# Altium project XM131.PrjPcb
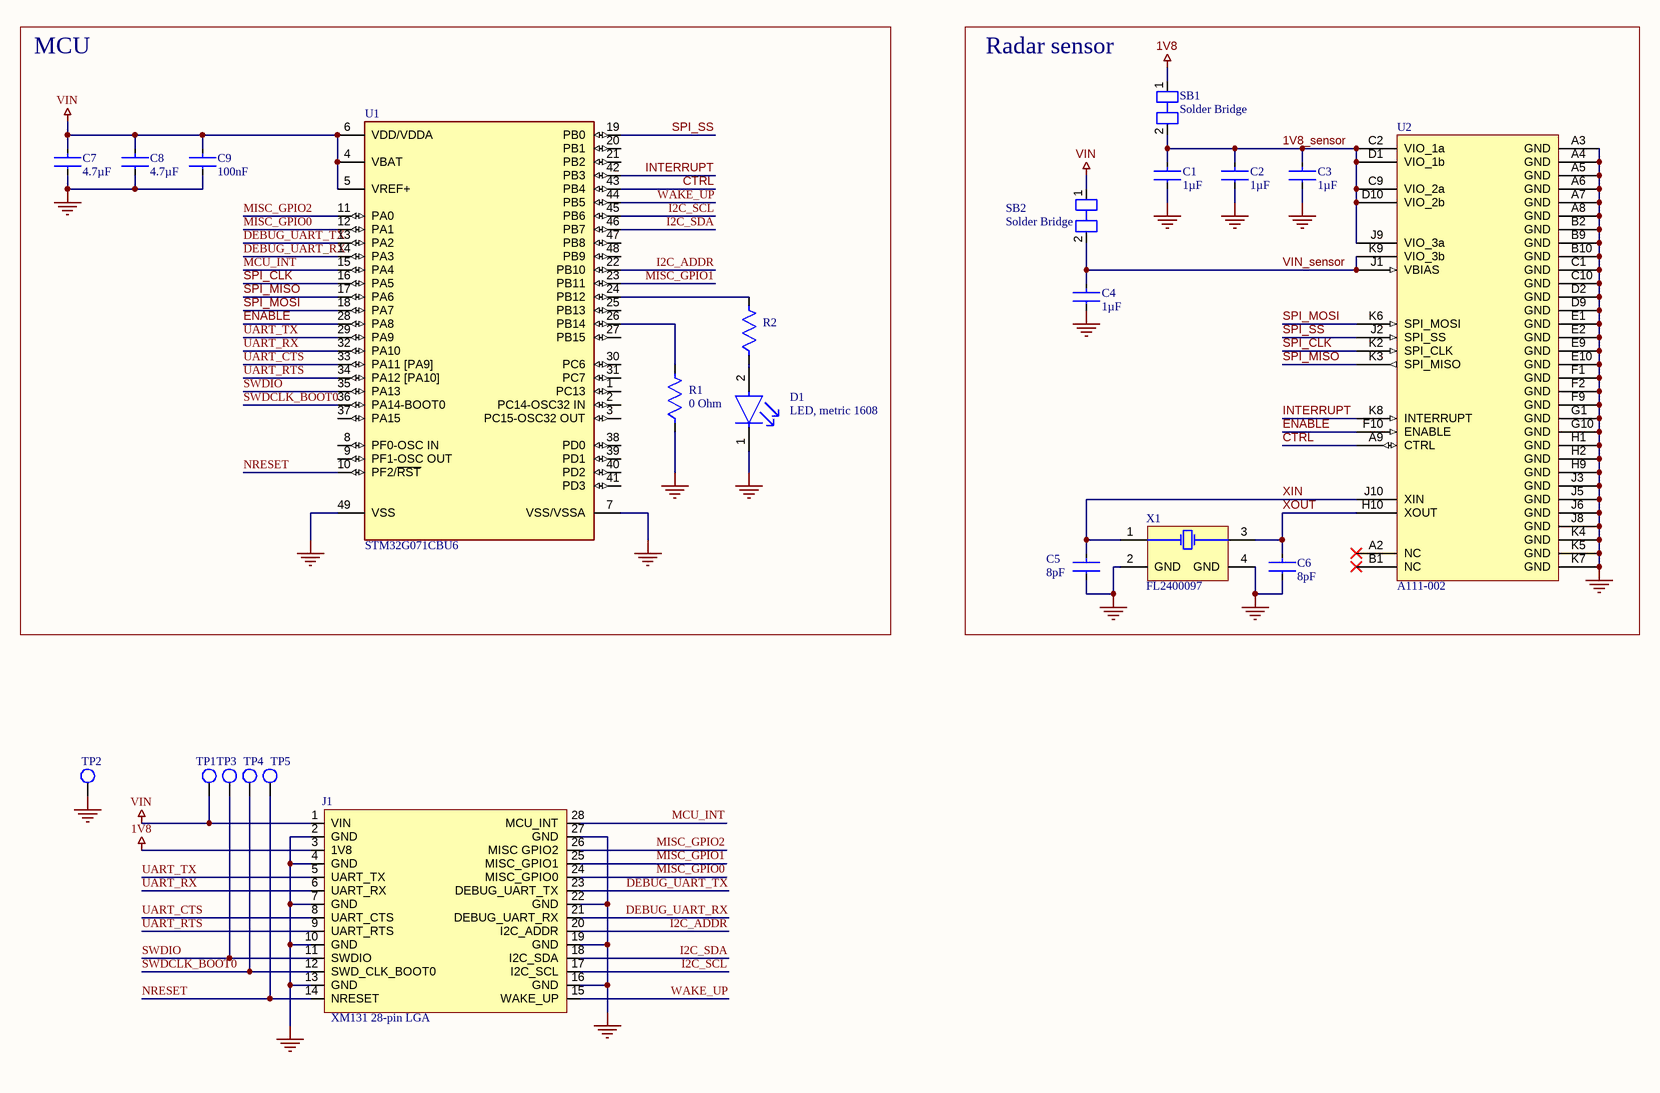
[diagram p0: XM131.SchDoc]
PCB_version: 1.1; PCBA_version: R1B; PB_number: 24
1 sheet, 23 parts. Net scope: global (net labels, ports and power ports of the same name join across sheets).
Board file: XM131.PcbDoc

## Sheet XM131.SchDoc: XM131 radar module
size 420 x 297 mm; CompanyName: Acconeer AB; DrawnBy: Jonas Långbacka; Address1: Acconeer AB; Address2: Västra Varvsgatan 19; Address3: 211 77 Malmö; Address4: Sweden; SheetNumber: 1; SheetTotal: 1

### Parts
C1  value 1µF  [CAPC0603X04N_no_silkscreen]  (hidden comment: Capacitor 1uF, metric 0603)
C2  value 1µF  [CAPC0603X04N_no_silkscreen]  (hidden comment: Capacitor 1uF, metric 0603)
C3  value 1µF  [CAPC0603X04N_no_silkscreen]  (hidden comment: Capacitor 1uF, metric 0603)
C4  value 1µF  [CAPC0603X04N_no_silkscreen]  (hidden comment: Capacitor 1uF, metric 0603)
C5  value 8pF  [CAPC0603X04N_no_silkscreen]  (hidden comment: Capacitor 8pF, metric 0603)
C6  value 8pF  [CAPC0603X04N_no_silkscreen]  (hidden comment: Capacitor 8pF, metric 0603)
C7  value 4.7µF  [CAPC1005X05L]  (hidden comment: Capacitor 4.7uF, metric 1005)
C8  value 4.7µF  [CAPC1005X05L]  (hidden comment: Capacitor 4.7uF, metric 1005)
C9  value 100nF  [CAPC1005X05L]  (hidden comment: Capacitor 100nF, metric 1005)
D1  LED, metric 1608  [DIOC1608X04L(green)]
J1  XM131 28-pin LGA  [LCCS127P1500X1800X0-28N]  (no BOM)
R1  value 0 Ohm  [RESC1005X04L]  (hidden comment: Resistor 0 Ohm, metric 1005)
R2  Resistor 340 Ohm, metric 1005  [RESC1005X04L]  (value not drawn)
SB1  Solder Bridge  [Solder Bridge-Footprint-1]  (net tie, no BOM)
SB2  Solder Bridge  [Solder Bridge-Footprint-1]  (net tie, no BOM)
TP1  Testpoint  [Testpoint_circular_0.8_no_silkscreen]  (value not drawn)  (no BOM)
TP2  Testpoint  [Testpoint_circular_0.8_no_silkscreen]  (value not drawn)  (no BOM)
TP3  Testpoint  [Testpoint_circular_0.8_no_silkscreen]  (value not drawn)  (no BOM)
TP4  Testpoint  [Testpoint_circular_0.8_no_silkscreen]  (value not drawn)  (no BOM)
TP5  Testpoint  [Testpoint_circular_0.8_no_silkscreen]  (value not drawn)  (no BOM)
U1  STM32G071CBU6  [QFN50P700X700X60_HS-49L]
U2  A111-002  [BGA50C50P10X10_520X550X90]
X1  FL2400097  [XTAL_320X260_no_silkscreen]

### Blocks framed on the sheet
MCU: C7-C9 D1 R1 R2 U1
Radar sensor: C1-C6 SB1 SB2 U2 X1

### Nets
1V8: J1.3(1V8) SB1.1
GND: C1.2 C2.2 C3.2 C4.2 C5.2 C6.2 C7.2 C8.2 C9.2 D1.1(C) J1.2(GND) J1.4(GND) J1.7(GND) J1.10(GND) J1.13(GND) J1.16(GND) J1.19(GND) J1.22(GND) J1.27(GND) R1.1 TP2.1 U1.7(VSS/VSSA) U1.49(VSS) U2.A3(GND) U2.A4(GND) U2.A5(GND) U2.A6(GND) U2.A7(GND) U2.A8(GND) U2.B2(GND) U2.B9(GND) U2.B10(GND) U2.C1(GND) U2.C10(GND) U2.D2(GND) U2.D9(GND) U2.E1(GND) U2.E2(GND) U2.E9(GND) U2.E10(GND) U2.F1(GND) U2.F2(GND) U2.F9(GND) U2.G1(GND) U2.G10(GND) U2.H1(GND) U2.H2(GND) U2.H9(GND) U2.J3(GND) U2.J5(GND) U2.J6(GND) U2.J8(GND) U2.K4(GND) U2.K5(GND) U2.K7(GND) X1.2(GND) X1.4(GND)
VIN: C7.1 C8.1 C9.1 J1.1(VIN) SB2.1 TP1.1 U1.4(VBAT) U1.5(VREF+) U1.6(VDD/VDDA)
1V8_sensor: C1.1 C2.1 C3.1 SB1.2 U2.C2(VIO_1a) U2.C9(VIO_2a) U2.D1(VIO_1b) U2.D10(VIO_2b) U2.J9(VIO_3a)
CTRL: U1.43(PB4) U2.A9(CTRL)
DEBUG_UART_RX: J1.21(DEBUG_UART_RX) U1.14(PA3)
DEBUG_UART_TX: J1.23(DEBUG_UART_TX) U1.13(PA2)
ENABLE: U1.28(PA8) U2.F10(ENABLE)
I2C_ADDR: J1.20(I2C_ADDR) U1.22(PB10)
I2C_SCL: J1.17(I2C_SCL) U1.45(PB6)
I2C_SDA: J1.18(I2C_SDA) U1.46(PB7)
INTERRUPT: U1.42(PB3) U2.K8(INTERRUPT)
MCU_INT: J1.28(MCU_INT) U1.15(PA4)
MISC_GPIO0: J1.24(MISC_GPIO0) U1.12(PA1)
MISC_GPIO1: J1.25(MISC_GPIO1) U1.23(PB11)
MISC_GPIO2: J1.26(MISC_GPIO2) U1.11(PA0)
NRESET: J1.14(NRESET) TP5.1 U1.10(PF2/~{RST})
SPI_CLK: U1.16(PA5) U2.K2(SPI_CLK)
SPI_MISO: U1.17(PA6) U2.K3(SPI_MISO)
SPI_MOSI: U1.18(PA7) U2.K6(SPI_MOSI)
SPI_SS: U1.19(PB0) U2.J2(SPI_SS)
SWDCLK_BOOT0: J1.12(SWD_CLK_BOOT0) TP4.1 U1.36(PA14-BOOT0)
SWDIO: J1.11(SWDIO) TP3.1 U1.35(PA13)
UART_CTS: J1.8(UART_CTS) U1.33(PA11_[PA9])
UART_RTS: J1.9(UART_RTS) U1.34(PA12_[PA10])
UART_RX: J1.6(UART_RX) U1.32(PA10)
UART_TX: J1.5(UART_TX) U1.29(PA9)
VIN_sensor: C4.1 SB2.2 U2.J1(VBIAS) U2.K9(VIO_3b)
WAKE_UP: J1.15(WAKE_UP) U1.44(PB5)
XIN: C5.1 U2.J10(XIN) X1.1(X1)
XOUT: C6.1 U2.H10(XOUT) X1.3(X2)
NetD1_2: D1.2(A) R2.1
NetR1_2: R1.2 U1.26(PB14)
NetR2_2: R2.2 U1.24(PB12)

Not connected (* = marked no-connect by the designer): U1 1(PC13) 2(PC14-OSC32_IN) 3(PC15-OSC32_OUT) 8(PF0-OSC_IN) 9(PF1-OSC_OUT) 20(PB1) 21(PB2) 25(PB13) 27(PB15) 30(PC6) 31(PC7) 37(PA15) 38(PD0) 39(PD1) 40(PD2) 41(PD3) 47(PB8) 48(PB9); U2 A2(NC)* B1(NC)*

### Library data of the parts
C1-C4 = CMP-001-00106-6: Generic 1uF SMD capacitor, metric 0603 (0201); Tolerance: 20%; Voltage Rating: 6.3V
C5 C6 = CMP-001-00107-4: Generic 8pF SMD capacitor, metric 0603 (0201); Voltage rating: 25V; Tolerance: 10%; Capacitor Type: Ceramic; Temperature Coefficient: C0G, NP0
C7 C8 = CMP-001-00105-4: Generic 4.7uF SMD capacitor, metric 1005 (0402); Voltage rating: 6.3V
C9 = CMP-001-00083-20: Generic 100nF SMD capacitor, metric 1005 (0402); Tolerance: 20%; Voltage rating: 6.3V
D1 = CMP-004-00037-3: Generic LED, metric 1608
J1 = CMP-002-00117-33: XM131 28-pin Land Grid Array (LGA), pitch 1.27 mm
R1 = CMP-009-00186-15: 0 Ohm generic SMD resistor, +/-1%, metric 1005 (0402); Package (imperial): 0402; Rating: 1%; Package (metric): 1005
R2 = CMP-009-00208-8: 340 Ohm generic SMD resistor, +/-1%, metric 1005 (0402); Value: 240Ohm; Package (imperial): 0402; Package (metric): 1005; Rating: 1%
SB1 SB2 = CMP-002-00092-19: Shorted Solder Bridge.
TP1-TP5 = CMP-00030-00001-9: Circular test point
U1 = CMP-020-00027-6: STM32G Series 128 KB Flash 36 kB RAM 64 MHz 32-Bit Microcontroller - UFQFPN-48; Manufacturer: ST
U2 = CMP-010-00029-2: Acconeer A111-002 pulsed coherent 60 GHz radar sensor; Manufacturer: Acconeer AB; Device revision: R2D
X1 = CMP-003-00035-9: Crystal 24MHz 9pF 4-Pin SMD; Manufacturer: Diodes Incorporated; ESR: 50

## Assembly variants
Production: not fitted D1 R5 R6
